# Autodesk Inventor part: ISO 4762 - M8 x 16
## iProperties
Comments: To add or edit properties for Autodesk Inventor files, use iProperties.
Created: 2004-08
Part Number: ISO 4762 - M8 x 16
Vendor: Autodesk Inc.
Document SubType Name: Modeling
Designer: John Blackburn
Material: Default
Description: Hexagon Socket Head Cap Screw
Standard: ISO 4762
Size Designation: M8 x 16
Alert: To add or edit properties for Autodesk Inventor files, use iProperties.
Control State: 0
Master: False
Checked Out: False
Shininess: 64.0
Length Units: 11269
Angle Units: 11279
Time Units: 11290
Mass Units: 11283
Length Display Precision: 3
Angle Display Precision: 2
Compacted: True
EGR: 1
Density: 0.0
Volumn: 0.0
Area: 0.0
PropertySet Name: Model Information
Author: John Blackburn
Revision Number: 8
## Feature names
1. Body [Revolution]
2. Slot [Extrusion]
3. Fillet1
4. Chamfer1
